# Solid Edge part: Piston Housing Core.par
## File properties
Author: Dan
Template: Normal.par
Last saved by: Dan
Revision: 17
Application: Solid Edge
Project Name: Piston Pump P52
Material: Sand
Density: 0.000006 kg/mm^3
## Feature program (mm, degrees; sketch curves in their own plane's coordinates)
sketch for "unnamed RevolvedProtrusion 1" plane through (51.2582, 2.8876, 0) normal (0, 0, 1) x-axis (1, 0, 0)
  line (-98.2582, 10.6821) -> (-98.5899, 20.1822)
  arc centre (-100.5887, 20.1124) radius 2 from (-100.5887, 22.1124) to (-98.5899, 20.1822) cw
  line (-100.5887, 22.1124) -> (-135.5887, 22.1124)
  arc centre (-135.5887, 20.1124) radius 2 from (-135.5887, 22.1124) to (-137.5875, 20.1822) ccw
  line (-137.5875, 20.1822) -> (-137.8693, 12.1124)
  line (-137.8693, 12.1124) -> (-141.2582, 12.1124)
  line (-141.2582, 12.1124) -> (-141.2582, -2.8876)
  line (-51.2582, -2.8876) -> (-51.2582, 9.717)
  line (-97.2588, 9.717) -> (-51.2582, 9.717)
  arc centre (-97.2588, 10.717) radius 1 from (-98.2582, 10.6821) to (-97.2588, 9.717) ccw
  dimension (linear) = 141.2582
revolve "unnamed RevolvedProtrusion 1" add full turn 360 deg about sketch line (-141.2582, -2.8876) -> (-51.2582, -2.8876)
sketch for "unnamed RevolvedProtrusion 2" plane through (0, 0, 0) normal (0, 0, 1) x-axis (1, 0, 0)
  line (0, 15.0163) -> (0, 0)
  arc centre (-10.3294, 0.1079) radius 44.3294 from (27, 24.0163) to (33.9999, 0) cw
  line (27, 28.0163) -> (27, 24.0163)
  line (19, 28.0163) -> (27, 28.0163)
  line (19, 28.0163) -> (19, 24.7172)
  arc centre (18, 24.7172) radius 1 from (19, 24.7172) to (18.3412, 23.7772) cw
  line (1.9763, 17.8363) -> (18.3412, 23.7772)
  arc centre (3, 15.0163) radius 3 from (0, 15.0163) to (1.9763, 17.8363) cw
revolve "unnamed RevolvedProtrusion 2" add full turn 360 deg about sketch line (33.9999, 0) -> (0, 0)
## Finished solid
Body 1: solid body, 17 faces, 16 edges, 1 vertex.
  Faces by surface: torus 6, cylinder 4, plane 4, cone 3
  Edges by curve: circle 16
Bounding box of the edges (mm; curved faces can reach further): 117.000 x 56.033 x 56.033, from (-90, -28.0163, -28.0163) to (27, 28.0163, 28.0163).
Cylindrical faces by radius (mm): R12.6046 x1, R15 x1, R25 x1, R28.0163 x1
Conical faces (half-angle, radius in mm at the cone's reference point): 19.9523 deg R23.7772 x1, 88 deg R13.5697 x1, 88 deg R23.0698 x1
Toroidal faces (ring radius, tube radius in mm): R0.1079 r44.3294 x1, R13.6046 r1 x1, R15.0163 r3 x1, R23 r2 x2, R24.7172 r1 x1
Planar faces by outward normal: +x 1, -x 3
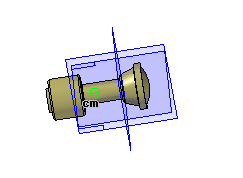
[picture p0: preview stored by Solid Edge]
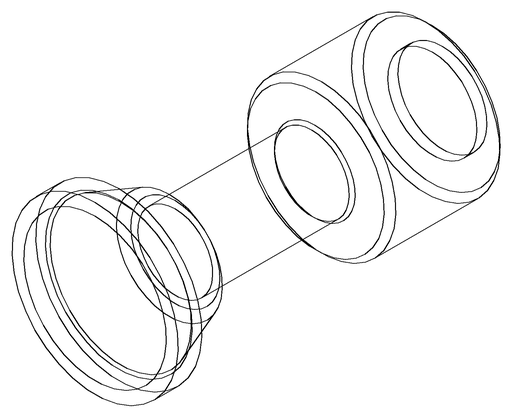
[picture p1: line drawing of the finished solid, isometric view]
